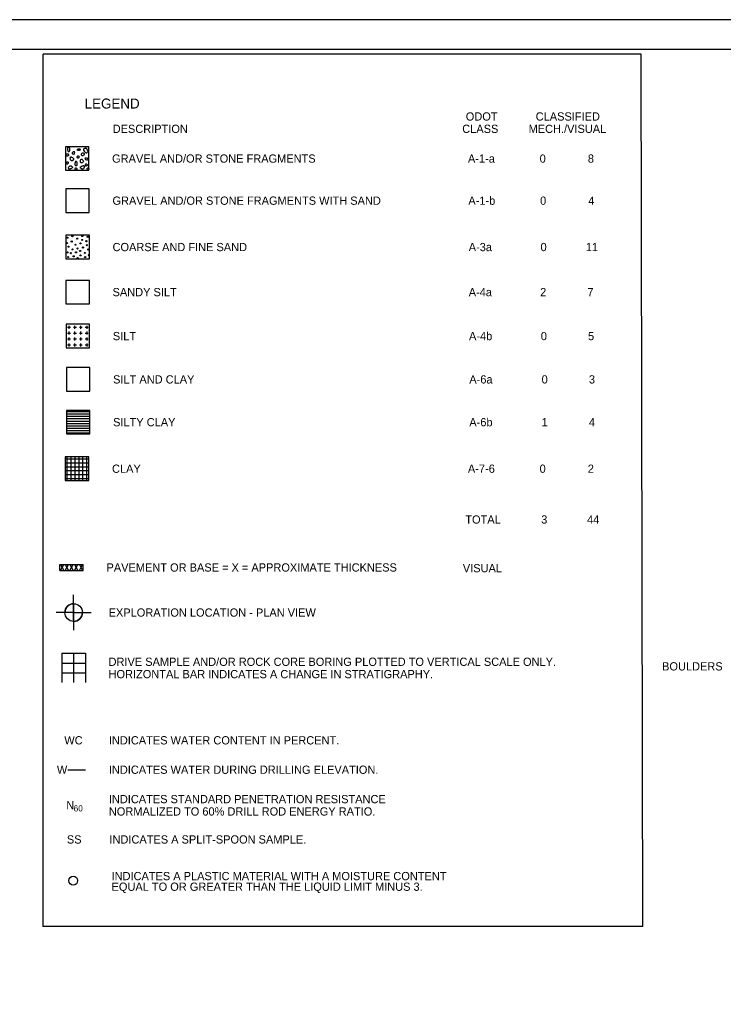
# Model space of a CAD drawing. Extents: x -11.4 to 84.1, y 11.1 to 59.
# Drawn here: x 14.02 to 25.98, y 31.52 to 48.43 of the extents above; entities that cross this region are included whole.
import ezdxf

# ---------------------------------------------------------------- set-up
doc = ezdxf.new("R2010")
doc.units = 0
for name, color, linetype in [('GT_Project_Cells', 7, 'Continuous'), ('GT_Project_Soil_Boring', 7, 'Continuous'), ('GT_Project_Soil_Layers', 7, 'Continuous'), ('SH_Border', 7, 'Continuous'), ('SH_Cut_Line', 7, 'Continuous'), ('SH_Data', 7, 'Continuous'), ('SH_Text', 7, 'Continuous')]:
    doc.layers.add(name, color=color, linetype=linetype)

msp = doc.modelspace()

# ---------------------------------------------------------------- linework, layer by layer
at = {"layer": 'GT_Project_Cells'}
msp.add_line((14.833, 35.675), (15.133, 35.675), dxfattribs=at)
at = {"layer": 'GT_Project_Soil_Boring'}
for p, q in [((14.932, 38.348), (14.932, 38.648)), ((14.932, 38.498), (14.932, 38.348)), ((14.932, 38.348), (14.632, 38.348)), ((14.932, 38.348), (14.782, 38.348)), ((14.932, 38.348), (14.932, 38.048)), ((14.932, 38.348), (15.232, 38.348)), ((14.932, 38.198), (14.932, 38.348)), ((14.932, 38.348), (15.082, 38.348)), ((14.731, 37.656), (15.131, 37.656)), ((14.731, 37.656), (14.731, 37.156)), ((14.931, 37.656), (14.931, 37.156)), ((15.131, 37.656), (15.131, 37.156)), ((14.731, 37.489), (15.131, 37.489)), ((14.731, 37.322), (15.131, 37.322))]:
    msp.add_line(p, q, dxfattribs=at)
msp.add_circle((14.932, 38.348), 0.15, dxfattribs=at)
for start, end in [(90, 180), (270, 360)]:
    msp.add_arc((14.932, 38.348), 0.15, start, end, dxfattribs=at)
at = {"layer": 'GT_Project_Soil_Layers'}
for p, q in [((14.709, 39.165), (14.763, 39.065)), ((14.709, 39.065), (14.763, 39.165)), ((14.789, 39.165), (14.843, 39.065)), ((14.789, 39.065), (14.843, 39.165)), ((14.869, 39.165), (14.923, 39.065)), ((14.869, 39.065), (14.923, 39.165)), ((14.949, 39.165), (15.003, 39.065)), ((14.949, 39.065), (15.003, 39.165)), ((15.029, 39.165), (15.083, 39.065)), ((15.029, 39.065), (15.083, 39.165))]:
    msp.add_line(p, q, dxfattribs=at)
at = {"layer": 'SH_Border'}
msp.add_lwpolyline([(4.289, 47.929), (36.289, 47.929), (36.289, 26.929), (4.289, 26.929)], close=True, dxfattribs=at)
at = {"layer": 'SH_Cut_Line'}
for p, q in [((14.791, 46.27), (14.791, 46.27)), ((15.191, 46.27), (15.191, 46.27)), ((14.956, 46.005), (14.952, 45.988)), ((14.791, 45.87), (14.791, 45.87)), ((15.191, 45.87), (15.191, 45.87)), ((14.799, 44.765), (14.799, 44.765)), ((15.199, 44.765), (15.199, 44.765)), ((14.799, 44.365), (14.799, 44.365)), ((15.199, 44.365), (15.199, 44.365)), ((14.804, 43.251), (14.804, 43.251)), ((14.829, 43.201), (14.879, 43.201)), ((14.854, 43.176), (14.854, 43.226)), ((14.854, 43.076), (14.854, 43.126)), ((14.929, 43.201), (14.979, 43.201)), ((14.954, 43.176), (14.954, 43.226)), ((14.954, 43.076), (14.954, 43.126)), ((15.029, 43.201), (15.079, 43.201)), ((15.054, 43.176), (15.054, 43.226)), ((15.054, 43.076), (15.054, 43.126)), ((15.129, 43.201), (15.154, 43.201)), ((15.154, 43.226), (15.154, 43.176)), ((15.154, 43.201), (15.179, 43.201)), ((15.154, 43.126), (15.154, 43.076)), ((15.204, 43.251), (15.204, 43.251)), ((14.829, 43.101), (14.879, 43.101)), ((14.829, 43.001), (14.879, 43.001)), ((14.854, 42.976), (14.854, 43.026)), ((14.929, 43.101), (14.979, 43.101)), ((14.929, 43.001), (14.979, 43.001)), ((14.954, 42.976), (14.954, 43.026)), ((15.029, 43.101), (15.079, 43.101)), ((15.029, 43.001), (15.079, 43.001)), ((15.054, 42.976), (15.054, 43.026)), ((15.129, 43.101), (15.154, 43.101)), ((15.129, 43.001), (15.154, 43.001)), ((15.154, 43.101), (15.179, 43.101)), ((15.154, 43.026), (15.154, 42.976)), ((15.154, 43.001), (15.179, 43.001)), ((14.804, 42.851), (14.804, 42.851)), ((14.829, 42.901), (14.879, 42.901)), ((14.854, 42.876), (14.854, 42.926)), ((14.929, 42.901), (14.979, 42.901)), ((14.954, 42.876), (14.954, 42.926)), ((15.029, 42.901), (15.079, 42.901)), ((15.054, 42.876), (15.054, 42.926)), ((15.129, 42.901), (15.154, 42.901)), ((15.154, 42.926), (15.154, 42.876)), ((15.154, 42.901), (15.179, 42.901)), ((15.204, 42.851), (15.204, 42.851)), ((14.808, 41.786), (14.808, 41.786)), ((15.208, 41.786), (15.208, 41.786)), ((14.808, 41.766), (15.208, 41.766)), ((14.808, 41.726), (15.208, 41.726)), ((14.808, 41.686), (15.208, 41.686)), ((14.808, 41.646), (15.208, 41.646)), ((14.808, 41.606), (15.208, 41.606)), ((14.808, 41.566), (15.208, 41.566)), ((14.808, 41.526), (15.208, 41.526)), ((14.808, 41.486), (15.208, 41.486)), ((14.808, 41.446), (15.208, 41.446)), ((14.808, 41.406), (15.208, 41.406)), ((14.808, 41.386), (14.808, 41.386)), ((15.208, 41.386), (15.208, 41.386)), ((14.79, 40.995), (14.79, 40.995)), ((14.79, 40.962), (15.19, 40.962)), ((14.823, 40.595), (14.823, 40.995)), ((14.89, 40.595), (14.89, 40.995)), ((14.957, 40.595), (14.957, 40.995)), ((15.023, 40.595), (15.023, 40.995)), ((15.09, 40.595), (15.09, 40.995)), ((15.157, 40.595), (15.157, 40.995)), ((15.19, 40.995), (15.19, 40.995)), ((14.79, 40.895), (15.19, 40.895)), ((14.79, 40.828), (15.19, 40.828)), ((14.79, 40.762), (15.19, 40.762)), ((14.79, 40.695), (15.19, 40.695)), ((14.79, 40.628), (15.19, 40.628)), ((14.79, 40.595), (14.79, 40.595)), ((15.19, 40.595), (15.19, 40.595))]:
    msp.add_line(p, q, dxfattribs=at)
msp.add_lwpolyline([(2.789, 26.429), (36.789, 26.429), (36.789, 48.429), (2.789, 48.429)], close=True, dxfattribs=at)
for centre, radius in [((14.829, 44.724), 0.00954), ((14.899, 44.659), 0.00954), ((14.91, 44.749), 0.00954), ((14.993, 44.708), 0.00954), ((15.077, 44.686), 0.00954), ((15.08, 44.752), 0.00954), ((15.148, 44.665), 0.00954), ((15.171, 44.739), 0.00954), ((14.817, 44.633), 0.00954), ((14.828, 44.475), 0.00954), ((14.846, 44.571), 0.00954), ((14.911, 44.525), 0.00954), ((14.965, 44.604), 0.00954), ((14.972, 44.475), 0.00954), ((14.997, 44.54), 0.00954), ((15.042, 44.498), 0.00954), ((15.049, 44.628), 0.00954), ((15.092, 44.558), 0.00954), ((15.156, 44.596), 0.00954), ((15.181, 44.523), 0.00954), ((14.837, 44.394), 0.00954), ((14.885, 44.461), 0.00954), ((14.932, 44.408), 0.00954), ((15, 44.375), 0.00954), ((15.048, 44.423), 0.00954), ((15.122, 44.465), 0.00954), ((15.128, 44.395), 0.00954), ((15.189, 44.426), 0.00954), ((14.925, 33.788), 0.0748)]:
    msp.add_circle(centre, radius, dxfattribs=at)
for points in [[(14.831, 46.206), (14.825, 46.231), (14.83, 46.251), (14.846, 46.26), (14.865, 46.251), (14.869, 46.22), (14.861, 46.195), (14.846, 46.189), (14.833, 46.2), (14.831, 46.206)], [(14.949, 46.166), (14.943, 46.145), (14.915, 46.15), (14.907, 46.167), (14.918, 46.181), (14.932, 46.185), (14.948, 46.182), (14.949, 46.166)], [(15.033, 46.212), (15.045, 46.219), (15.043, 46.232), (15.029, 46.238), (15.008, 46.234), (14.996, 46.224), (14.994, 46.214), (15.008, 46.209), (15.02, 46.207), (15.033, 46.212)], [(15.072, 46.157), (15.063, 46.139), (15.077, 46.119), (15.095, 46.12), (15.111, 46.143), (15.105, 46.163), (15.085, 46.166), (15.072, 46.157)], [(15.164, 46.227), (15.171, 46.194), (15.161, 46.174), (15.151, 46.167), (15.136, 46.171), (15.124, 46.183), (15.099, 46.213), (15.102, 46.232), (15.11, 46.236), (15.126, 46.244), (15.141, 46.245), (15.15, 46.242), (15.158, 46.237), (15.164, 46.227)], [(14.838, 46.12), (14.85, 46.128), (14.848, 46.141), (14.833, 46.147), (14.813, 46.143), (14.801, 46.132), (14.799, 46.122), (14.813, 46.118), (14.825, 46.116), (14.837, 46.12)], [(14.817, 46.011), (14.805, 45.998), (14.813, 45.981), (14.828, 45.977), (14.835, 45.986), (14.837, 46.001), (14.833, 46.013), (14.827, 46.017), (14.821, 46.016), (14.817, 46.011)], [(14.884, 46.042), (14.87, 46.066), (14.872, 46.084), (14.878, 46.092), (14.89, 46.094), (14.903, 46.088), (14.931, 46.071), (14.934, 46.056), (14.929, 46.05), (14.919, 46.04), (14.907, 46.035), (14.9, 46.034), (14.892, 46.036), (14.884, 46.042)], [(14.991, 45.961), (14.994, 45.991), (14.986, 46.015), (14.971, 46.022), (14.958, 46.011), (14.956, 46.005)], [(15.014, 46.08), (15.026, 46.094), (15.018, 46.11), (15.003, 46.115), (14.996, 46.105), (14.994, 46.09), (14.999, 46.079), (15.004, 46.074), (15.01, 46.076), (15.014, 46.08)], [(15.08, 46.004), (15.098, 46.025), (15.085, 46.051), (15.063, 46.057), (15.051, 46.043), (15.049, 46.019), (15.055, 46.001), (15.064, 45.995), (15.073, 45.996), (15.08, 46.004)], [(15.164, 46.075), (15.176, 46.068), (15.174, 46.055), (15.16, 46.048), (15.139, 46.052), (15.127, 46.063), (15.125, 46.073), (15.139, 46.077), (15.151, 46.08), (15.164, 46.075)], [(14.861, 45.939), (14.847, 45.916), (14.849, 45.897), (14.855, 45.889), (14.867, 45.888), (14.88, 45.894), (14.908, 45.91), (14.911, 45.925), (14.906, 45.931), (14.896, 45.941), (14.884, 45.947), (14.877, 45.947), (14.869, 45.945), (14.861, 45.939)], [(14.952, 45.988), (14.95, 45.98), (14.955, 45.96), (14.971, 45.951), (14.99, 45.96), (14.991, 45.961)], [(14.976, 45.876), (14.988, 45.89), (14.98, 45.907), (14.965, 45.911), (14.958, 45.901), (14.956, 45.886), (14.961, 45.875), (14.966, 45.871), (14.972, 45.872), (14.976, 45.876)], [(15.098, 45.898), (15.112, 45.921), (15.111, 45.94), (15.105, 45.948), (15.093, 45.949), (15.079, 45.944), (15.051, 45.927), (15.048, 45.912), (15.054, 45.906), (15.064, 45.896), (15.076, 45.891), (15.083, 45.89), (15.091, 45.892), (15.098, 45.898)], [(15.153, 45.945), (15.165, 45.958), (15.157, 45.975), (15.142, 45.979), (15.135, 45.97), (15.133, 45.955), (15.137, 45.943), (15.143, 45.939), (15.149, 45.94), (15.153, 45.945)], [(15.17, 45.908), (15.158, 45.894), (15.167, 45.877), (15.181, 45.873), (15.188, 45.883), (15.19, 45.898), (15.186, 45.909), (15.181, 45.913), (15.174, 45.912), (15.17, 45.908)]]:
    msp.add_spline(points, degree=3, dxfattribs=at)
at = {"layer": 'SH_Data'}
for p, q in [((14.415, 33.009), (14.415, 47.848)), ((24.59, 47.848), (14.415, 47.848)), ((24.62, 33.009), (24.59, 47.848)), ((14.696, 39.065), (14.696, 39.165)), ((14.696, 39.165), (15.096, 39.165)), ((14.696, 39.065), (15.096, 39.065)), ((15.096, 39.065), (15.096, 39.165)), ((24.62, 33.009), (14.409, 33.009))]:
    msp.add_line(p, q, dxfattribs=at)
for points in [[(14.791, 45.87), (15.191, 45.87), (15.191, 46.27), (14.791, 46.27)], [(14.798, 45.154), (15.198, 45.154), (15.198, 45.554), (14.798, 45.554)], [(14.799, 44.365), (15.199, 44.365), (15.199, 44.765), (14.799, 44.765)], [(14.799, 43.598), (15.199, 43.598), (15.199, 43.998), (14.799, 43.998)], [(14.804, 42.851), (15.204, 42.851), (15.204, 43.251), (14.804, 43.251)], [(14.808, 42.114), (15.208, 42.114), (15.208, 42.514), (14.808, 42.514)], [(14.808, 41.386), (15.208, 41.386), (15.208, 41.786), (14.808, 41.786)], [(14.79, 40.595), (15.19, 40.595), (15.19, 40.995), (14.79, 40.995)]]:
    msp.add_lwpolyline(points, close=True, dxfattribs=at)

# ---------------------------------------------------------------- texts
at = {"layer": 'GT_Project_Cells'}
msp.add_text('W', height=0.14, dxfattribs=at).set_placement((14.647, 35.605))
at = {"layer": 'SH_Text'}
for s, height, p in [('LEGEND', 0.17, (15.12, 46.921)), (' ODOT ', 0.14, (21.553, 46.716)), ('CLASSIFIED', 0.14, (22.795, 46.716)), ('DESCRIPTION', 0.14, (15.596, 46.506)), ('CLASS', 0.14, (21.545, 46.506)), ('MECH./VISUAL', 0.14, (22.674, 46.506)), ('GRAVEL AND/OR STONE FRAGMENTS                 ', 0.14, (15.586, 46)), (' A-1-a ', 0.14, (21.59, 46)), (' 0 ', 0.14, (22.81, 46)), (' 8 ', 0.14, (23.63, 46)), ('GRAVEL AND/OR STONE FRAGMENTS WITH SAND       ', 0.14, (15.593, 45.284)), (' A-1-b ', 0.14, (21.597, 45.284)), (' 0 ', 0.14, (22.818, 45.284)), (' 4 ', 0.14, (23.638, 45.284)), ('COARSE AND FINE SAND                         ', 0.14, (15.594, 44.495)), (' A-3a  ', 0.14, (21.603, 44.495)), ('0', 0.14, (22.877, 44.495)), ('11', 0.14, (23.647, 44.495)), ('SANDY SILT                                   ', 0.14, (15.594, 43.728)), (' A-4a  ', 0.14, (21.603, 43.728)), (' 2 ', 0.14, (22.818, 43.728)), (' 7 ', 0.14, (23.622, 43.728)), (' A-4b  ', 0.14, (21.608, 42.981)), ('SILT                                         ', 0.14, (15.599, 42.981)), ('0', 0.14, (22.882, 42.981)), ('5', 0.14, (23.685, 42.981)), ('SILT AND CLAY                                ', 0.14, (15.603, 42.244)), (' A-6a  ', 0.14, (21.613, 42.244)), (' 0 ', 0.14, (22.844, 42.244)), (' 3 ', 0.14, (23.648, 42.244)), ('SILTY CLAY                                   ', 0.14, (15.603, 41.516)), (' A-6b  ', 0.14, (21.613, 41.516)), (' 1 ', 0.14, (22.844, 41.516)), (' 4 ', 0.14, (23.648, 41.516)), ('CLAY                                               ', 0.14, (15.585, 40.725)), (' A-7-6 ', 0.14, (21.589, 40.725)), (' 0 ', 0.14, (22.809, 40.725)), (' 2 ', 0.14, (23.629, 40.725)), (' TOTAL ', 0.14, (21.545, 39.861)), (' 3 ', 0.14, (22.836, 39.861)), (' 44', 0.14, (23.617, 39.861)), ('PAVEMENT OR BASE = X = APPROXIMATE THICKNESS', 0.14, (15.491, 39.045)), ('VISUAL ', 0.14, (21.555, 39.033)), ('EXPLORATION LOCATION - PLAN VIEW', 0.14, (15.527, 38.278)), ('DRIVE SAMPLE AND/OR ROCK CORE BORING PLOTTED TO VERTICAL SCALE ONLY.', 0.14, (15.526, 37.441)), ('BOULDERS', 0.14, (24.946, 37.363)), ('HORIZONTAL BAR INDICATES A CHANGE IN STRATIGRAPHY.', 0.14, (15.526, 37.231)), ('WC', 0.14, (14.773, 36.105)), ('INDICATES WATER CONTENT IN PERCENT.', 0.14, (15.531, 36.105)), ('INDICATES WATER DURING DRILLING ELEVATION.', 0.14, (15.531, 35.605)), ('INDICATES STANDARD PENETRATION RESISTANCE', 0.14, (15.531, 35.105)), ('N', 0.14, (14.807, 35)), ('60', 0.105, (14.932, 34.965)), ('NORMALIZED TO 60% DRILL ROD ENERGY RATIO.', 0.14, (15.531, 34.895)), ('SS', 0.14, (14.817, 34.419)), ('INDICATES A SPLIT-SPOON SAMPLE.', 0.14, (15.541, 34.419)), ('INDICATES A PLASTIC MATERIAL WITH A MOISTURE CONTENT ', 0.14, (15.577, 33.796)), ('EQUAL TO OR GREATER THAN THE LIQUID LIMIT MINUS 3.', 0.14, (15.577, 33.615))]:
    msp.add_text(s, height=height, dxfattribs=at).set_placement(p)

doc.saveas('drawing.dxf')
